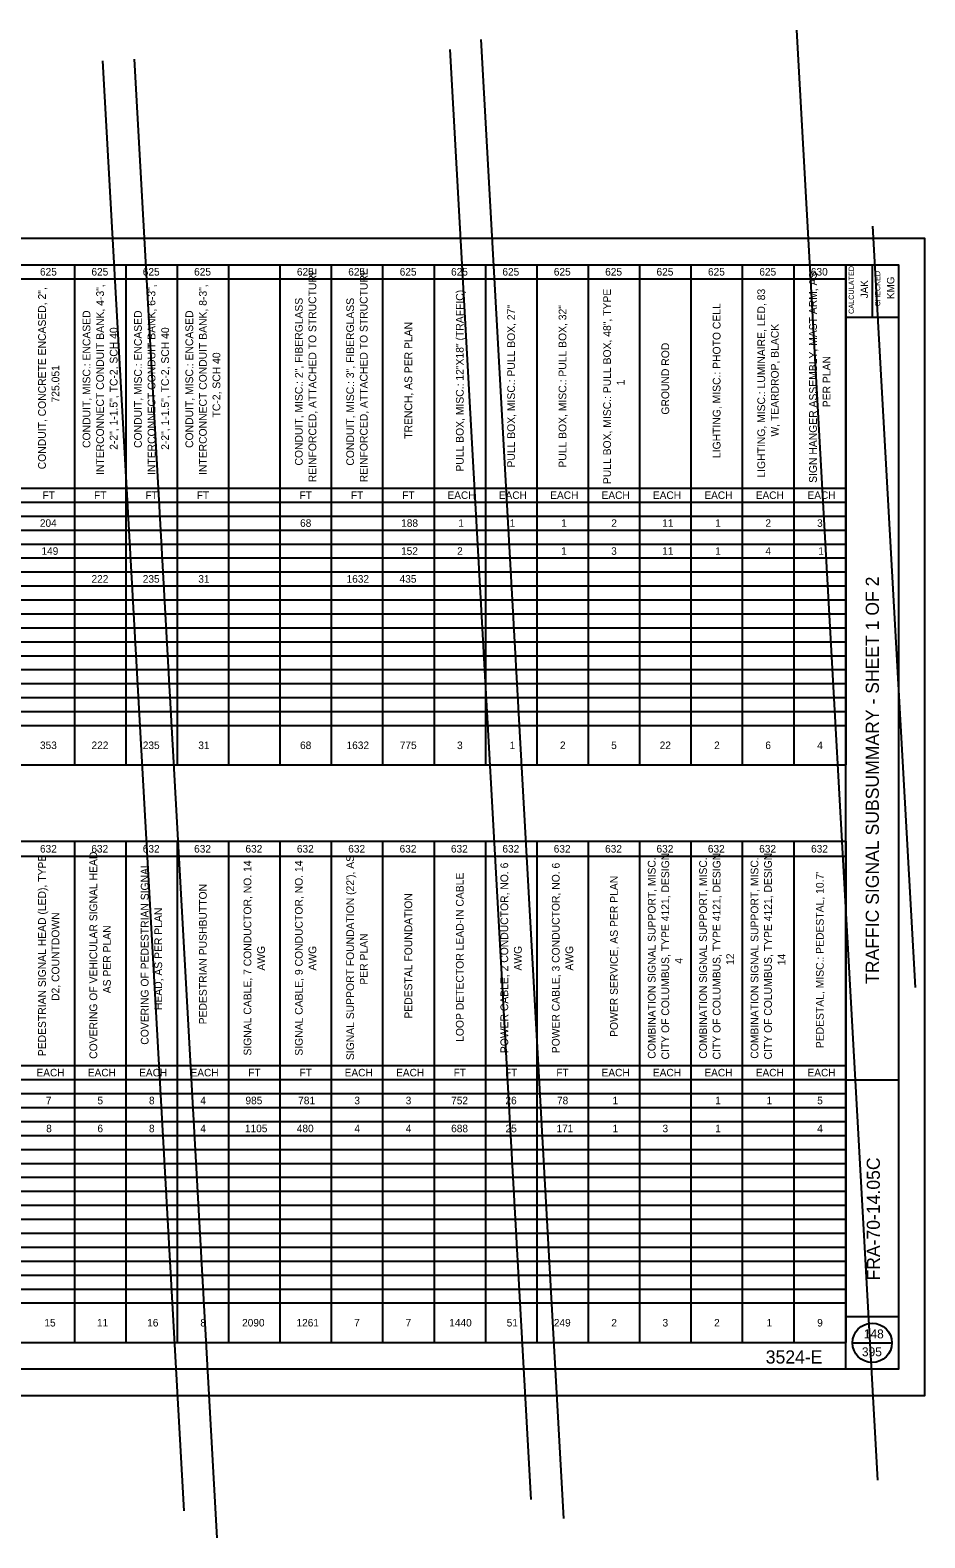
# Model space of a CAD drawing. Extents: x 1822281 to 1823981, y 709999 to 711443.
# Drawn here: x 1823131 to 1823981, y 710010 to 711443 of the extents above; entities that cross this region are included whole.
import ezdxf

# ---------------------------------------------------------------- set-up
doc = ezdxf.new("R2010")
doc.units = 0
for name, color, linetype in [('SC_Scratch1', 7, 'Continuous'), ('SH_Border', 7, 'Continuous'), ('SH_Cut_Line', 7, 'Continuous'), ('SH_Data', 7, 'Continuous'), ('SH_Text', 7, 'Continuous')]:
    doc.layers.add(name, color=color, linetype=linetype)

msp = doc.modelspace()

# ---------------------------------------------------------------- linework, layer by layer
at = {"layer": 'SC_Scratch1'}
for p, q in [((1823859, 711443.4), (1823936.2, 710064.7)), ((1823529.5, 711425), (1823606.7, 710046.3)), ((1823559, 711434.5), (1823637.8, 710028.4)), ((1823199.6, 711414.3), (1823276.8, 710035.6)), ((1823229.5, 711416), (1823308.3, 710009.9)), ((1823931.5, 711257.1), (1823972, 710533.3))]:
    msp.add_line(p, q, dxfattribs=at)
at = {"layer": 'SH_Border'}
for p, q in [((1823906.1, 710170.4), (1823906.1, 711220.4)), ((1823931.1, 711220.4), (1823931.1, 711170.4)), ((1823906.1, 711170.4), (1823956.1, 711170.4)), ((1823906.1, 710445.4), (1823956.1, 710445.4)), ((1823906.1, 710220.4), (1823956.1, 710220.4))]:
    msp.add_line(p, q, dxfattribs=at)
msp.add_lwpolyline([(1822381.1, 711220.4), (1823956.1, 711220.4), (1823956.1, 710170.4), (1822381.1, 710170.4)], close=True, dxfattribs=at)
at = {"layer": 'SH_Cut_Line'}
msp.add_lwpolyline([(1822281.1, 710145.4), (1823981.1, 710145.4), (1823981.1, 711245.4), (1822281.1, 711245.4)], close=True, dxfattribs=at)
at = {"layer": 'SH_Data'}
msp.add_line((1823912.4, 710195.4), (1823949.9, 710195.4), dxfattribs=at)
msp.add_circle((1823931.1, 710195.4), 18.7, dxfattribs=at)
at = {"layer": 'SH_Text'}
for p, q in [((1822381.1, 711220.4), (1823906.1, 711220.4)), ((1822831, 711207.1), (1823906.1, 711207.1)), ((1823172.8, 711220.4), (1823172.8, 710744.8)), ((1823221.7, 711220.4), (1823221.7, 710744.8)), ((1823270.5, 711220.4), (1823270.5, 710744.8)), ((1823319.3, 711220.4), (1823319.3, 710744.8)), ((1823368.2, 711220.4), (1823368.2, 710744.8)), ((1823417, 711220.4), (1823417, 710744.8)), ((1823465.8, 711220.4), (1823465.8, 710744.8)), ((1823514.7, 711220.4), (1823514.7, 710744.8)), ((1823563.5, 711220.4), (1823563.5, 710744.8)), ((1823612.3, 711220.4), (1823612.3, 710744.8)), ((1823661.2, 711220.4), (1823661.2, 710744.8)), ((1823710, 711220.4), (1823710, 710744.8)), ((1823758.8, 711220.4), (1823758.8, 710744.8)), ((1823807.6, 711220.4), (1823807.6, 710744.8)), ((1823856.5, 711220.4), (1823856.5, 710744.8)), ((1823906.1, 711220.4), (1823906.1, 710744.8)), ((1822831, 711008), (1823906.1, 711008)), ((1822381.1, 710994.7), (1823906.1, 710994.7)), ((1822381.1, 710981.4), (1823906.1, 710981.4)), ((1822381.1, 710968.1), (1823906.1, 710968.1)), ((1822381.1, 710954.8), (1823906.1, 710954.8)), ((1822381.1, 710941.6), (1823906.1, 710941.6)), ((1822381.1, 710928.3), (1823906.1, 710928.3)), ((1822381.1, 710915), (1823906.1, 710915)), ((1822381.1, 710901.7), (1823906.1, 710901.7)), ((1822381.1, 710888.5), (1823906.1, 710888.5)), ((1822381.1, 710875.2), (1823906.1, 710875.2)), ((1822381.1, 710861.9), (1823906.1, 710861.9)), ((1822381.1, 710848.6), (1823906.1, 710848.6)), ((1822381.1, 710835.4), (1823906.1, 710835.4)), ((1822381.1, 710822.1), (1823906.1, 710822.1)), ((1822381.1, 710808.8), (1823906.1, 710808.8)), ((1822381.1, 710795.5), (1823906.1, 710795.5)), ((1822381.1, 710782.3), (1823906.1, 710782.3)), ((1822381.1, 710744.8), (1823906.1, 710744.8)), ((1822381.1, 710672.2), (1823906.1, 710672.2)), ((1823172.8, 710672.2), (1823172.8, 710195.8)), ((1823221.7, 710672.2), (1823221.7, 710195.8)), ((1823270.5, 710672.2), (1823270.5, 710195.8)), ((1823319.3, 710672.2), (1823319.3, 710195.8)), ((1823368.2, 710672.2), (1823368.2, 710195.8)), ((1823417, 710672.2), (1823417, 710195.8)), ((1823465.8, 710672.2), (1823465.8, 710195.8)), ((1823514.7, 710672.2), (1823514.7, 710195.8)), ((1823563.5, 710672.2), (1823563.5, 710195.8)), ((1823612.3, 710672.2), (1823612.3, 710195.8)), ((1823661.2, 710672.2), (1823661.2, 710195.8)), ((1823710, 710672.2), (1823710, 710195.8)), ((1823758.8, 710672.2), (1823758.8, 710195.8)), ((1823807.6, 710672.2), (1823807.6, 710195.8)), ((1823856.5, 710672.2), (1823856.5, 710195.8)), ((1823906.1, 710672.2), (1823906.1, 710195.8)), ((1822831, 710658.1), (1823906.1, 710658.1)), ((1822831, 710459), (1823906.1, 710459)), ((1822381.1, 710445.7), (1823906.1, 710445.7)), ((1822381.1, 710432.4), (1823906.1, 710432.4)), ((1822381.1, 710419.1), (1823906.1, 710419.1)), ((1822381.1, 710405.9), (1823906.1, 710405.9)), ((1822381.1, 710392.6), (1823906.1, 710392.6)), ((1822381.1, 710379.3), (1823906.1, 710379.3)), ((1822381.1, 710366), (1823906.1, 710366)), ((1822381.1, 710352.8), (1823906.1, 710352.8)), ((1822381.1, 710339.5), (1823906.1, 710339.5)), ((1822381.1, 710326.2), (1823906.1, 710326.2)), ((1822381.1, 710312.9), (1823906.1, 710312.9)), ((1822381.1, 710299.6), (1823906.1, 710299.6)), ((1822381.1, 710286.4), (1823906.1, 710286.4)), ((1822381.1, 710273.1), (1823906.1, 710273.1)), ((1822381.1, 710259.8), (1823906.1, 710259.8)), ((1822381.1, 710246.5), (1823906.1, 710246.5)), ((1822381.1, 710233.3), (1823906.1, 710233.3)), ((1822381.1, 710195.8), (1823906.1, 710195.8))]:
    msp.add_line(p, q, dxfattribs=at)

# ---------------------------------------------------------------- texts
at = {"layer": 'SH_Data'}
for s, height, p in [('CALCULATED', 5, (1823913.7, 711173.6)), ('CHECKED', 5, (1823938.7, 711180.8)), ('TRAFFIC SIGNAL SUBSUMMARY - SHEET 1 OF 2', 12.5, (1823937.4, 710536.6))]:
    msp.add_text(s, height=height, rotation=90, dxfattribs=at).set_placement(p)
at = {"layer": 'SH_Text'}
for s, height, p in [('625', 7.18, (1823140.1, 711210.1)), ('625', 7.18, (1823189, 711210.1)), ('625', 7.18, (1823237.8, 711210.1)), ('625', 7.18, (1823286.6, 711210.1)), ('625', 7.18, (1823384.3, 711210.1)), ('625', 7.18, (1823433.1, 711210.1)), ('625', 7.18, (1823482, 711210.1)), ('625', 7.18, (1823530.8, 711210.1)), ('625', 7.18, (1823579.6, 711210.1)), ('625', 7.18, (1823628.5, 711210.1)), ('625', 7.18, (1823677.3, 711210.1)), ('625', 7.18, (1823726.1, 711210.1)), ('625', 7.18, (1823775, 711210.1)), ('625', 7.18, (1823823.8, 711210.1)), ('630', 7.18, (1823872.8, 711210.1)), ('FT', 7.18, (1823142.6, 710997.7)), ('FT', 7.18, (1823191.5, 710997.7)), ('FT', 7.18, (1823240.3, 710997.7)), ('FT', 7.18, (1823289.1, 710997.7)), ('FT', 7.18, (1823386.8, 710997.7)), ('FT', 7.18, (1823435.6, 710997.7)), ('FT', 7.18, (1823484.4, 710997.7)), ('EACH', 7.18, (1823527.4, 710997.7)), ('EACH', 7.18, (1823576.2, 710997.7)), ('EACH', 7.18, (1823625.1, 710997.7)), ('EACH', 7.18, (1823673.9, 710997.7)), ('EACH', 7.18, (1823722.7, 710997.7)), ('EACH', 7.18, (1823771.6, 710997.7)), ('EACH', 7.18, (1823820.4, 710997.7)), ('EACH', 7.18, (1823869.6, 710997.7)), ('204', 7.18, (1823140, 710971.2)), ('68', 7.18, (1823387.3, 710971.2)), ('188', 7.18, (1823483.4, 710971.2)), ('1', 7.18, (1823537.7, 710971.2)), ('1', 7.18, (1823586.5, 710971.2)), ('1', 7.18, (1823635.4, 710971.2)), ('2', 7.18, (1823683.1, 710971.2)), ('11', 7.18, (1823731.5, 710971.2)), ('1', 7.18, (1823781.9, 710971.2)), ('2', 7.18, (1823829.6, 710971.2)), ('3', 7.18, (1823878.7, 710971.2)), ('149', 7.18, (1823141.5, 710944.6)), ('152', 7.18, (1823483.3, 710944.6)), ('2', 7.18, (1823536.6, 710944.6)), ('1', 7.18, (1823635.4, 710944.6)), ('3', 7.18, (1823683, 710944.6)), ('11', 7.18, (1823731.5, 710944.6)), ('1', 7.18, (1823781.9, 710944.6)), ('4', 7.18, (1823829.6, 710944.6)), ('1', 7.18, (1823879.9, 710944.6)), ('222', 7.18, (1823189.1, 710918.1)), ('235', 7.18, (1823237.8, 710918.1)), ('31', 7.18, (1823290.6, 710918.1)), ('1632', 7.18, (1823431.5, 710918.1)), ('435', 7.18, (1823481.9, 710918.1)), ('353', 7.18, (1823140.1, 710759.9)), ('222', 7.18, (1823189.1, 710759.9)), ('235', 7.18, (1823237.8, 710759.9)), ('31', 7.18, (1823290.6, 710759.9)), ('68', 7.18, (1823387.3, 710759.9)), ('1632', 7.18, (1823431.5, 710759.9)), ('775', 7.18, (1823482.1, 710759.9)), ('3', 7.18, (1823536.5, 710759.9)), ('1', 7.18, (1823586.5, 710759.9)), ('2', 7.18, (1823634.3, 710759.9)), ('5', 7.18, (1823683, 710759.9)), ('22', 7.18, (1823729.1, 710759.9)), ('2', 7.18, (1823780.8, 710759.9)), ('6', 7.18, (1823829.5, 710759.9)), ('4', 7.18, (1823878.8, 710759.9)), ('632', 7.18, (1823140.1, 710661.5)), ('632', 7.18, (1823188.9, 710661.5)), ('632', 7.18, (1823237.8, 710661.5)), ('632', 7.18, (1823286.6, 710661.5)), ('632', 7.18, (1823335.4, 710661.5)), ('632', 7.18, (1823384.3, 710661.5)), ('632', 7.18, (1823433.1, 710661.5)), ('632', 7.18, (1823481.9, 710661.5)), ('632', 7.18, (1823530.7, 710661.5)), ('632', 7.18, (1823579.6, 710661.5)), ('632', 7.18, (1823628.4, 710661.5)), ('632', 7.18, (1823677.2, 710661.5)), ('632', 7.18, (1823726.1, 710661.5)), ('632', 7.18, (1823774.9, 710661.5)), ('632', 7.18, (1823823.7, 710661.5)), ('632', 7.18, (1823873, 710661.5)), ('EACH', 7.18, (1823136.8, 710448.7)), ('EACH', 7.18, (1823185.6, 710448.7)), ('EACH', 7.18, (1823234.4, 710448.7)), ('EACH', 7.18, (1823283.2, 710448.7)), ('FT', 7.18, (1823338, 710448.7)), ('FT', 7.18, (1823386.8, 710448.7)), ('EACH', 7.18, (1823429.7, 710448.7)), ('EACH', 7.18, (1823478.6, 710448.7)), ('FT', 7.18, (1823533.3, 710448.7)), ('FT', 7.18, (1823582.1, 710448.7)), ('FT', 7.18, (1823630.9, 710448.7)), ('EACH', 7.18, (1823673.9, 710448.7)), ('EACH', 7.18, (1823722.7, 710448.7)), ('EACH', 7.18, (1823771.6, 710448.7)), ('EACH', 7.18, (1823820.4, 710448.7)), ('EACH', 7.18, (1823869.6, 710448.7)), ('7', 7.18, (1823145.7, 710422.2)), ('5', 7.18, (1823194.7, 710422.2)), ('8', 7.18, (1823243.7, 710422.2)), ('4', 7.18, (1823292.5, 710422.2)), ('985', 7.18, (1823335.4, 710422.2)), ('781', 7.18, (1823385.5, 710422.2)), ('3', 7.18, (1823438.9, 710422.2)), ('3', 7.18, (1823487.7, 710422.2)), ('752', 7.18, (1823530.9, 710422.2)), ('26', 7.18, (1823582.5, 710422.2)), ('78', 7.18, (1823631.5, 710422.2)), ('1', 7.18, (1823684.2, 710422.2)), ('1', 7.18, (1823781.9, 710422.2)), ('1', 7.18, (1823830.7, 710422.2)), ('5', 7.18, (1823878.8, 710422.2)), ('8', 7.18, (1823146, 710395.6)), ('6', 7.18, (1823194.7, 710395.6)), ('8', 7.18, (1823243.7, 710395.6)), ('4', 7.18, (1823292.5, 710395.6)), ('1105', 7.18, (1823334.9, 710395.6)), ('480', 7.18, (1823384.2, 710395.6)), ('4', 7.18, (1823439, 710395.6)), ('4', 7.18, (1823487.8, 710395.6)), ('688', 7.18, (1823530.9, 710395.6)), ('25', 7.18, (1823582.6, 710395.6)), ('171', 7.18, (1823631, 710395.6)), ('1', 7.18, (1823684.2, 710395.6)), ('3', 7.18, (1823731.8, 710395.6)), ('1', 7.18, (1823781.9, 710395.6)), ('4', 7.18, (1823878.8, 710395.6)), ('15', 7.18, (1823144.3, 710210.9)), ('11', 7.18, (1823194.3, 710210.9)), ('16', 7.18, (1823242, 710210.9)), ('8', 7.18, (1823292.5, 710210.9)), ('2090', 7.18, (1823332.2, 710210.9)), ('1261', 7.18, (1823383.9, 710210.9)), ('7', 7.18, (1823438.7, 710210.9)), ('7', 7.18, (1823487.6, 710210.9)), ('1440', 7.18, (1823529.1, 710210.9)), ('51', 7.18, (1823583.7, 710210.9)), ('249', 7.18, (1823628.5, 710210.9)), ('2', 7.18, (1823683.1, 710210.9)), ('3', 7.18, (1823731.8, 710210.9)), ('2', 7.18, (1823780.8, 710210.9)), ('1', 7.18, (1823830.7, 710210.9)), ('9', 7.18, (1823878.8, 710210.9)), ('148', 8.5, (1823923.1, 710199.6)), ('395', 8.5, (1823921.3, 710182.6))]:
    msp.add_text(s, height=height, dxfattribs=at).set_placement(p)
for s, height, rotation, p in [('REINFORCED, ATTACHED TO STRUCTURE', 7.365, 90, (1823402.7, 711013.6)), ('REINFORCED, ATTACHED TO STRUCTURE', 7.365, 90, (1823451.5, 711013.6)), ('SIGN HANGER ASSEMBLY, MAST ARM, AS', 7.365, 90, (1823878.5, 711013)), ('KMG', 7, 90, (1823952.1, 711187.8)), ('CONDUIT, CONCRETE ENCASED, 2",', 7.365, 90, (1823145.7, 711025.9)), ('INTERCONNECT CONDUIT BANK, 4-3",', 7.365, 90, (1823200.9, 711020.5)), ('INTERCONNECT CONDUIT BANK, 6-3",', 7.365, 90, (1823249.8, 711020.5)), ('INTERCONNECT CONDUIT BANK, 8-3",', 7.365, 90, (1823298.6, 711020.5)), ('PULL BOX, MISC.: 12"X18" (TRAFFIC)', 7.365, 90, (1823542.8, 711023.7)), ('PULL BOX, MISC.: PULL BOX, 48", TYPE', 7.365, 90, (1823682.8, 711011.8)), ('LIGHTING, MISC.: LUMINAIRE, LED, 83', 7.365, 90, (1823829.3, 711018)), ('JAK', 7, 90, (1823927.1, 711188.5)), ('CONDUIT, MISC.: 2", FIBERGLASS', 7.365, 90, (1823389.8, 711029.5)), ('CONDUIT, MISC.: 3", FIBERGLASS', 7.365, 90, (1823438.6, 711029.4)), ('PULL BOX, MISC.: PULL BOX, 27"', 7.365, 90, (1823591.6, 711027.6)), ('PULL BOX, MISC.: PULL BOX, 32"', 7.365, 90, (1823640.4, 711027.5)), ('LIGHTING, MISC.: PHOTO CELL', 7.365, 90, (1823786.9, 711036.6)), ('CONDUIT, MISC.: ENCASED', 7.365, 90, (1823188, 711046.2)), ('CONDUIT, MISC.: ENCASED', 7.365, 90, (1823236.9, 711046.2)), ('CONDUIT, MISC.: ENCASED', 7.365, 90, (1823285.7, 711046.2)), ('TRENCH, AS PER PLAN', 7.365, 90, (1823493.9, 711054.9)), ('W, TEARDROP, BLACK', 7.365, 90, (1823842.2, 711057)), ('2-2", 1-1.5", TC-2, SCH 40', 7.365, 90, (1823213.8, 711044.4)), ('2-2", 1-1.5", TC-2, SCH 40', 7.365, 90, (1823262.7, 711044.4)), ('TC-2, SCH 40', 7.365, 90, (1823311.5, 711075.2)), ('GROUND ROD', 7.36, 90, (1823738.1, 711077.9)), ('725.051', 7.36, 90, (1823158.5, 711089.4)), ('PER PLAN', 7.36, 90, (1823891.4, 711084.9)), ('1', 7.36, 90, (1823695.7, 711105.7)), ('COVERING OF VEHICULAR SIGNAL HEAD,', 7.365, 90, (1823194.5, 710465.4)), ('PEDESTRIAN SIGNAL HEAD (LED), TYPE', 7.365, 90, (1823145.7, 710467.9)), ('COVERING OF PEDESTRIAN SIGNAL', 7.365, 90, (1823243.3, 710478.8)), ('SIGNAL CABLE, 7 CONDUCTOR, NO. 14', 7.365, 90, (1823341, 710468.5)), ('SIGNAL CABLE, 9 CONDUCTOR, NO. 14', 7.365, 90, (1823389.8, 710468.4)), ("SIGNAL SUPPORT FOUNDATION (22'), AS", 7.365, 90, (1823438.6, 710464.2)), ('POWER CABLE, 2 CONDUCTOR, NO. 6', 7.365, 90, (1823585.1, 710470.8)), ('POWER CABLE, 3 CONDUCTOR, NO. 6', 7.365, 90, (1823634, 710470.7)), ('COMBINATION SIGNAL SUPPORT, MISC.:', 7.365, 90, (1823725.2, 710465.5)), ('CITY OF COLUMBUS, TYPE 4121, DESIGN', 7.365, 90, (1823738.1, 710464.8)), ('COMBINATION SIGNAL SUPPORT, MISC.:', 7.365, 90, (1823774, 710465.5)), ('CITY OF COLUMBUS, TYPE 4121, DESIGN', 7.365, 90, (1823786.9, 710464.8)), ('COMBINATION SIGNAL SUPPORT, MISC.:', 7.365, 90, (1823822.9, 710465.5)), ('CITY OF COLUMBUS, TYPE 4121, DESIGN', 7.365, 90, (1823835.7, 710464.8)), ('LOOP DETECTOR LEAD-IN CABLE', 7.365, 90, (1823542.8, 710481.5)), ('POWER SERVICE, AS PER PLAN', 7.365, 90, (1823689.3, 710486.2)), ("PEDESTAL, MISC.: PEDESTAL, 10.7'", 7.365, 90, (1823885, 710475.5)), ('PEDESTRIAN PUSHBUTTON', 7.365, 90, (1823298.6, 710498.2)), ('PEDESTAL FOUNDATION', 7.365, 90, (1823493.9, 710503.6)), ('HEAD, AS PER PLAN', 7.365, 90, (1823256.2, 710511.7)), ('D2, COUNTDOWN', 7.365, 90, (1823158.5, 710520.4)), ('AS PER PLAN', 7.365, 90, (1823207.4, 710527.7)), ('PER PLAN', 7.36, 90, (1823451.5, 710535.9)), ('AWG', 7.36, 90, (1823353.9, 710549.3)), ('AWG', 7.36, 90, (1823402.7, 710549.3)), ('AWG', 7.36, 90, (1823598, 710549.3)), ('AWG', 7.36, 90, (1823646.9, 710549.3)), ('12', 7.36, 90, (1823799.8, 710554.6)), ('14', 7.36, 90, (1823848.6, 710554.3)), ('4', 7.36, 90, (1823751, 710555.8)), ('FRA-70-14.05C', 12.5, 90, (1823938.4, 710254.6)), ('3524-E', 12.5, 359.9999, (1823829.9, 710175.7))]:
    msp.add_text(s, height=height, rotation=rotation, dxfattribs=at).set_placement(p)

doc.saveas('drawing.dxf')
